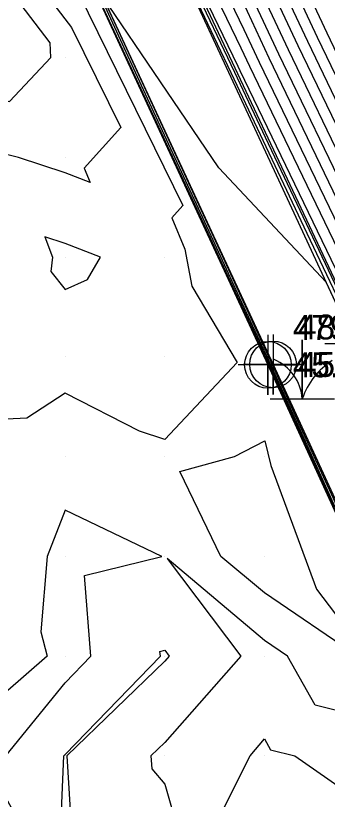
# Model space of a CAD drawing. Extents: x 2090860 to 2091277, y 159470 to 160080.
# Drawn here: x 2090915 to 2090946.3, y 159905.6 to 159984.2 of the extents above; entities that cross this region are included whole.
import ezdxf

# ---------------------------------------------------------------- set-up
doc = ezdxf.new("R2010")
doc.units = 0
for name, color, linetype in [('DTM Contours Major', 7, 'Continuous'), ('DTM Contours Minor', 7, 'Continuous'), ('Exist DTM Breakline', 7, 'Continuous'), ('Exist DTM Breakline Cogo Elevation', 7, 'Continuous'), ('Exist DTM Breakline Cogo Number', 7, 'Continuous'), ('Exist DTM Breakline Cogo Point CELL', 7, 'Continuous'), ('Exist DTM QL2 LIDAR Elevation Point', 7, 'Continuous'), ('Exist Hydro Swamp or Marsh', 7, 'Continuous')]:
    doc.layers.add(name, color=color, linetype=linetype)

msp = doc.modelspace()

# ---------------------------------------------------------------- linework, layer by layer
at = {"layer": 'DTM Contours Major'}
for points in [[(2090915.092, 160045.426), (2090922.919, 160028.827), (2090925.677, 160023.356), (2090935.836, 160001.778), (2090938.587, 159996.284), (2090939.794, 159993.785), (2090945.294, 159982.053), (2090947.597, 159977.284), (2090958.084, 159954.914), (2090958.856, 159953.218), (2090962.481, 159945.429), (2090964.802, 159940.332), (2090975.096, 159918.212), (2090976.136, 159916.102), (2090980.927, 159905.726), (2090983.402, 159900.704)], [(2090910.606, 160043.392), (2090913.448, 160037.366), (2090921.532, 160021.331), (2090926.001, 160011.839), (2090934.731, 159994.403), (2090938.563, 159986.471), (2090941.418, 159980.382), (2090948.738, 159965.223), (2090954.329, 159953.296), (2090956.792, 159947.89), (2090958.683, 159943.825), (2090966.198, 159927.322), (2090971.199, 159916.575), (2090974.729, 159909.419), (2090977.08, 159904.325)], [(2090907.426, 160041.969), (2090911.786, 160032.768), (2090917.984, 160019.602), (2090928.464, 159997.339), (2090930.876, 159992.521), (2090937.332, 159979.157), (2090937.542, 159978.71), (2090949.879, 159953.162), (2090950.574, 159951.679), (2090954.727, 159942.562), (2090954.886, 159942.222), (2090962.638, 159925.196), (2090966.571, 159916.855), (2090967.464, 159914.985), (2090973.015, 159903.605)], [(2090878.864, 160034.967), (2090897.091, 160039.466), (2090903.651, 160025.321), (2090910.038, 160012.34), (2090912.377, 160007.335), (2090915.967, 160000.292), (2090918.562, 159992.105), (2090919.202, 159989.241), (2090921.362, 159986.426), (2090931.819, 159965.183), (2090930.712, 159963.948), (2090932.018, 159960.802), (2090932.724, 159957.106), (2090937.257, 159949.444), (2090930, 159941.72), (2090927.457, 159942.543), (2090920, 159946.378), (2090916.149, 159943.851), (2090910, 159943.546), (2090902.359, 159947.641), (2090900, 159946.671), (2090893.58, 159946.42), (2090892.56, 159944.88)], [(2090923.538, 159960), (2090920, 159961.356), (2090917.97, 159962.03), (2090918.719, 159960), (2090918.547, 159958.547), (2090920, 159956.766), (2090922.256, 159957.744), (2090923.538, 159960)], [(2090949.577, 159919.577), (2090949.337, 159920), (2090940, 159926.334), (2090935.634, 159930), (2090931.506, 159938.494), (2090937.002, 159940), (2090940.061, 159941.589), (2090940.636, 159939.105), (2090945.228, 159926.717), (2090950.221, 159920.15), (2090950, 159919.471), (2090949.577, 159919.577)], [(2090920, 159899.567), (2090919.474, 159900.526), (2090919.876, 159910), (2090920, 159910.152), (2090929.56, 159920), (2090929.52, 159920.48), (2090930, 159920.599), (2090930.454, 159920), (2090930, 159919.485), (2090920.179, 159910), (2090920.747, 159900.747), (2090921.387, 159900), (2090920, 159899.567)]]:
    msp.add_lwpolyline(points, dxfattribs=at)
at = {"layer": 'DTM Contours Minor'}
for points in [[(2090916.214, 160045.934), (2090925.287, 160026.693), (2090926.714, 160023.863), (2090938.295, 159999.263), (2090939.55, 159996.755), (2090940.102, 159995.614), (2090946.263, 159982.47), (2090947.312, 159980.299), (2090959.023, 159955.318), (2090959.373, 159954.55), (2090963.43, 159945.83), (2090964.452, 159943.584), (2090976.07, 159918.621), (2090976.488, 159917.773), (2090981.889, 159906.077), (2090983.02, 159903.782)], [(2090913.971, 160044.918), (2090920.551, 160030.962), (2090924.641, 160022.85), (2090933.377, 160004.293), (2090937.623, 159995.814), (2090939.486, 159991.957), (2090944.325, 159981.635), (2090947.882, 159974.268), (2090957.145, 159954.509), (2090958.34, 159951.886), (2090961.531, 159945.028), (2090965.151, 159937.08), (2090974.122, 159917.803), (2090975.785, 159914.432), (2090979.965, 159905.376)], [(2090912.849, 160044.409), (2090918.183, 160033.097), (2090923.605, 160022.344), (2090930.919, 160006.809), (2090936.659, 159995.344), (2090939.178, 159990.128), (2090943.356, 159981.217), (2090948.168, 159971.253), (2090956.207, 159954.105), (2090957.824, 159950.554), (2090960.582, 159944.627), (2090965.5, 159933.827), (2090973.148, 159917.393), (2090975.433, 159912.761), (2090979.004, 159905.026)], [(2090911.728, 160043.901), (2090915.815, 160035.231), (2090922.569, 160021.838), (2090928.46, 160009.324), (2090935.695, 159994.873), (2090938.871, 159988.3), (2090942.387, 159980.799), (2090948.453, 159968.238), (2090955.268, 159953.701), (2090957.308, 159949.222), (2090959.632, 159944.226), (2090965.849, 159930.575), (2090972.174, 159916.984), (2090975.081, 159911.09), (2090978.042, 159904.675)], [(2090909.485, 160042.884), (2090911.08, 160039.501), (2090920.496, 160020.825), (2090923.543, 160014.354), (2090933.768, 159993.933), (2090938.255, 159984.643), (2090940.449, 159979.964), (2090949.023, 159962.207), (2090953.39, 159952.892), (2090956.276, 159946.558), (2090957.734, 159943.424), (2090966.547, 159924.07), (2090970.225, 159916.166), (2090974.377, 159907.749), (2090976.119, 159903.975)], [(2090906.701, 160041.663), (2090916.132, 160021.763), (2090917.301, 160019.278), (2090919.911, 160013.734), (2090930.148, 159992.169), (2090935.256, 159981.379), (2090936.616, 159978.521), (2090944.254, 159962.401), (2090949.505, 159951.363), (2090952.287, 159945.521), (2090954.079, 159941.72), (2090957.972, 159933.464), (2090966.981, 159914.593), (2090968.004, 159912.496), (2090972.898, 159902.775)], [(2090907.064, 160041.816), (2090913.959, 160027.266), (2090917.643, 160019.44), (2090925.862, 160001.979), (2090930.45, 159992.315), (2090932.739, 159987.48), (2090936.984, 159978.555), (2090940.085, 159972.01), (2090949.879, 159951.423), (2090950.719, 159949.661), (2090954.36, 159941.937), (2090962.272, 159925.16), (2090967.223, 159914.789), (2090970.51, 159908.05), (2090973.119, 159902.868)], [(2090907.788, 160042.123), (2090909.613, 160038.271), (2090916.596, 160023.437), (2090918.424, 160019.813), (2090918.625, 160019.385), (2090931.84, 159992.992), (2090937.64, 159980.985), (2090938.511, 159979.128), (2090949.594, 159956.177), (2090951.513, 159952.083), (2090955.244, 159943.894), (2090955.835, 159942.622), (2090967.245, 159917.565), (2090968.277, 159915.347), (2090973.673, 159904.407)], [(2090908.363, 160042.375), (2090908.712, 160041.635), (2090919.46, 160020.319), (2090921.084, 160016.87), (2090932.804, 159993.462), (2090937.948, 159982.814), (2090939.48, 159979.546), (2090949.308, 159959.192), (2090952.452, 159952.487), (2090955.76, 159945.226), (2090956.784, 159943.023), (2090966.896, 159920.817), (2090969.251, 159915.756), (2090974.025, 159906.078), (2090975.157, 159903.624)], [(2090898.298, 160040.07), (2090902.561, 160030.534), (2090909.741, 160015.052), (2090910.823, 160012.853), (2090918.991, 159995.373), (2090922.033, 159989.405), (2090928.025, 159976.37), (2090934.637, 159962.164), (2090937.707, 159955.499), (2090940.625, 159949.227), (2090948.523, 159931.794), (2090953.056, 159921.956), (2090965.045, 159895.337)], [(2090868.102, 160032.133), (2090896.569, 160039.16), (2090900.606, 160030.455), (2090908.186, 160015.051), (2090909.143, 160012.603), (2090909.31, 160012.043), (2090909.771, 160010.051), (2090914.18, 159996.146), (2090915.655, 159989.533), (2090920.643, 159983.036), (2090925.583, 159973.001), (2090921.92, 159968.915), (2090922.513, 159967.487), (2090920, 159968.451), (2090915.329, 159970), (2090910, 159971.335), (2090905.305, 159974.695), (2090900, 159975.694), (2090891.754, 159970), (2090890, 159969.104), (2090886.285, 159967.429), (2090886.339, 159960.983), (2090883.674, 159965.814)], [(2090900, 159985.502), (2090905.379, 159980), (2090910, 159976.693), (2090914.412, 159975.588), (2090918.548, 159980), (2090918.502, 159981.498), (2090912.109, 159989.826)], [(2090923.078, 159986.602), (2090934.563, 159961.929), (2090935.674, 159959.518), (2090940.467, 159949.216), (2090951.052, 159925.852), (2090951.531, 159923.784), (2090952.026, 159922.449), (2090952.564, 159921.741), (2090950, 159913.865), (2090945.097, 159915.097), (2090942.31, 159920), (2090940, 159921.567), (2090930.226, 159929.774), (2090937.638, 159920), (2090930, 159911.339), (2090928.613, 159910), (2090928.694, 159908.694), (2090930, 159907.169), (2090932.034, 159900)], [(2090971.838, 159903.298), (2090965.559, 159913.825), (2090960.005, 159918.329), (2090953.785, 159940.417), (2090952.656, 159942.311), (2090953.018, 159943.141), (2090949.131, 159951.303), (2090948.423, 159952.793), (2090946.196, 159957.493), (2090935.425, 159968.942), (2090923.729, 159986.244), (2090932.971, 159966.138), (2090934.711, 159962.399), (2090939.74, 159951.48), (2090940.783, 159949.239), (2090943.605, 159943.01), (2090953.294, 159921.983), (2090957.425, 159912.812), (2090965.766, 159894.719)], [(2090920, 159894.958), (2090913.88, 159906.12), (2090914.045, 159910), (2090920, 159917.33), (2090922.592, 159920), (2090921.926, 159928.074), (2090929.709, 159930), (2090920, 159934.618), (2090918.196, 159930), (2090917.56, 159922.44), (2090918.208, 159920), (2090910, 159912.893), (2090903.542, 159922.916)], [(2090940, 159891.292), (2090936.919, 159900), (2090935.698, 159904.302), (2090938.586, 159910), (2090940, 159911.701), (2090940.616, 159910.616), (2090943.071, 159910), (2090950, 159905.156), (2090963.729, 159895.221), (2090953.729, 159896.271), (2090950, 159897.832), (2090943.458, 159896.542), (2090940, 159891.292)]]:
    msp.add_lwpolyline(points, dxfattribs=at)
at = {"layer": 'Exist DTM Breakline'}
for points in [[(2091019.809, 159801.913), (2091004.418, 159836.946), (2090986.475, 159875.987), (2090967.517, 159915.028), (2090950.041, 159951.449), (2090930.695, 159992.433), (2090908.049, 160042.233)], [(2091019.111, 159801.55), (2091003.076, 159836.513), (2090986.016, 159875.809), (2090966.872, 159914.505), (2090949.073, 159951.294), (2090930.109, 159992.15), (2090906.432, 160041.549)], [(2090898.02, 160040.012), (2090922.126, 159989.703), (2090940.871, 159949.246), (2090967.299, 159891.857)], [(2090895.734, 160038.669), (2090921.911, 159989.017), (2090940.353, 159949.207), (2090966.689, 159891.716)]]:
    msp.add_lwpolyline(points, dxfattribs=at)
at = {"layer": 'Exist DTM Breakline Cogo Point CELL'}
for points in [[(2090949.073, 159954.294), (2090949.073, 159948.294), (2090949.073, 159951.294), (2090952.073, 159951.294), (2090946.073, 159951.294)], [(2090940.353, 159952.207), (2090940.353, 159946.207), (2090940.353, 159949.207), (2090943.353, 159949.207), (2090937.353, 159949.207)], [(2090940.871, 159952.246), (2090940.871, 159946.246), (2090940.871, 159949.246), (2090943.871, 159949.246), (2090937.871, 159949.246)]]:
    msp.add_lwpolyline(points, dxfattribs=at)
for centre in [(2090940.353, 159949.207), (2090940.871, 159949.246)]:
    msp.add_circle(centre, 2.344, dxfattribs=at)
at = {"layer": 'Exist DTM QL2 LIDAR Elevation Point'}
for p, q in [((2090920, 159980), (2090920, 159980)), ((2090920, 159970), (2090920, 159970)), ((2090920, 159960), (2090920, 159960)), ((2090930, 159960), (2090930, 159960)), ((2090920, 159950), (2090920, 159950)), ((2090930, 159950), (2090930, 159950)), ((2090920, 159940), (2090920, 159940)), ((2090930, 159940), (2090930, 159940)), ((2090940, 159940), (2090940, 159940)), ((2090920, 159930), (2090920, 159930)), ((2090930, 159930), (2090930, 159930)), ((2090940, 159930), (2090940, 159930)), ((2090920, 159920), (2090920, 159920)), ((2090930, 159920), (2090930, 159920)), ((2090940, 159920), (2090940, 159920)), ((2090920, 159910), (2090920, 159910)), ((2090930, 159910), (2090930, 159910)), ((2090940, 159910), (2090940, 159910))]:
    msp.add_line(p, q, dxfattribs=at)
at = {"layer": 'Exist Hydro Swamp or Marsh'}
msp.add_line((2090943.806, 159948.471), (2090943.806, 159948.471), dxfattribs=at)
msp.add_lwpolyline([(2090940.581, 159945.797), (2090943.807, 159945.797), (2090943.807, 159951.714), (2090943.807, 159945.797), (2090947.032, 159945.797)], dxfattribs=at)
for centre, radius, start, end in [((2090939.207, 159945.464), 4.612, 4.14034, 67.53497), ((2090950.648, 159943.524), 7.208, 122.12745, 161.62219)]:
    msp.add_arc(centre, radius, start, end, dxfattribs=at)

# ---------------------------------------------------------------- texts
at = {"layer": 'Exist DTM Breakline Cogo Elevation'}
for s, p in [('45.93', (2090942.853, 159947.957)), ('45.11', (2090943.371, 159947.996))]:
    msp.add_text(s, height=2.5, dxfattribs=at).set_placement(p)
at = {"layer": 'Exist DTM Breakline Cogo Number'}
for s, p in [('479', (2090942.853, 159951.707)), ('480', (2090943.371, 159951.746))]:
    msp.add_text(s, height=2.5, dxfattribs=at).set_placement(p)

doc.saveas('drawing.dxf')
